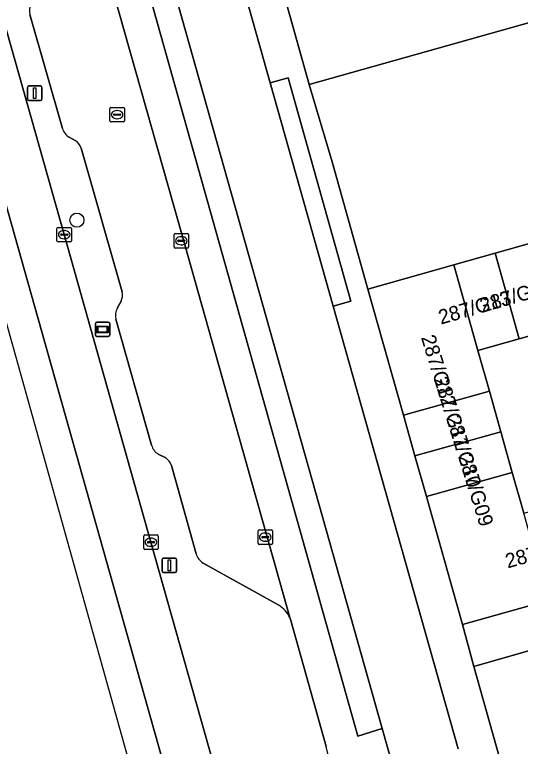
# Model space of a CAD drawing. Extents: x 159680 to 160786, y 387323 to 388340.
# Drawn here: x 159736.2 to 159770.9, y 387944.8 to 387995.1 of the extents above; entities that cross this region are included whole.
import ezdxf

# ---------------------------------------------------------------- set-up
doc = ezdxf.new("R2010")
doc.units = 0
for name, color, linetype in [('IMGEO_Berm_groen', 7, 'Continuous'), ('IMGEO_Boom', 7, 'Continuous'), ('IMGEO_Erf', 7, 'Continuous'), ('IMGEO_Kolk', 7, 'Continuous'), ('IMGEO_Lichtmast', 7, 'Continuous'), ('IMGEO_OVBaan_gesloten', 7, 'Continuous'), ('IMGEO_Pand', 7, 'Continuous'), ('IMGEO_Pand_nummerreeks', 7, 'Continuous'), ('IMGEO_Parkeervlak_open', 7, 'Continuous'), ('IMGEO_Rijbaan_lokaal_gesloten', 7, 'Continuous'), ('IMGEO_Rijbaan_lokaal_open', 7, 'Continuous'), ('IMGEO_Rijbaan_regionaal_gesloten', 7, 'Continuous'), ('IMGEO_Rioolput', 7, 'Continuous'), ('IMGEO_Voetpad_open', 7, 'Continuous'), ('IMGEO_Wegwijzer', 7, 'Continuous')]:
    doc.layers.add(name, color=color, linetype=linetype)

msp = doc.modelspace()

# ---------------------------------------------------------------- linework, layer by layer
at = {"layer": 'IMGEO_Berm_groen'}
for points in [[(159715.024, 388067.618), (159715.751, 388064.431), (159715.988, 388063.449), (159716.233, 388062.473), (159717.284, 388058.854), (159722.145, 388041.542), (159727.852, 388021.312), (159733.85, 388000.16), (159739.567, 387979.98), (159745.531, 387958.814), (159750.399, 387941.515), (159752.767, 387933.007), (159752.834, 387932.851)], [(159739.441, 387987.286), (159737.2, 387995.117)], [(159740.315, 387986.458), (159739.908, 387986.68)], [(159743.542, 387976.042), (159740.723, 387985.94)], [(159743.218, 387974.92), (159743.482, 387975.405)], [(159745.578, 387965.499), (159743.123, 387974.154)], [(159746.565, 387964.628), (159746.032, 387964.879)], [(159748.638, 387958.018), (159746.942, 387964.105)], [(159754.336, 387954.481), (159749.116, 387957.374)], [(159757.589, 387944.769), (159755.159, 387953.438), (159755.075, 387953.635)]]:
    msp.add_lwpolyline(points, dxfattribs=at)
for centre, radius, start, end in [((159738.236, 387995.366), 1.065, 151.5729, 193.506), ((159740.55, 387987.658), 1.17, 198.5337, 236.7039), ((159739.864, 387985.683), 0.897, 16.6604, 59.7907), ((159742.594, 387975.81), 0.976, 335.4919, 13.7463), ((159744.175, 387974.412), 1.083, 152.0546, 193.8058), ((159746.583, 387965.758), 1.038, 194.4791, 237.9484), ((159745.504, 387963.466), 1.573, 23.9627, 47.6085), ((159749.768, 387958.358), 1.18, 196.7211, 236.4471), ((159753.179, 387952.725), 2.103, 25.6488, 56.627), ((159746.164, 387941.8), 11.804, 335.9534, 14.5668)]:
    msp.add_arc(centre, radius, start, end, dxfattribs=at)
at = {"layer": 'IMGEO_Boom'}
msp.add_circle((159740.436, 387980.974), 0.489, dxfattribs=at)
at = {"layer": 'IMGEO_Erf'}
msp.add_lwpolyline([(159760.456, 387976.237), (159766.359, 387977.9), (159769.209, 387978.703), (159772.059, 387979.506), (159774.909, 387980.309), (159777.759, 387981.111), (159780.609, 387981.914), (159783.459, 387982.717), (159786.309, 387983.52), (159789.159, 387984.323), (159792.009, 387985.126), (159794.859, 387985.929), (159797.709, 387986.732), (159800.559, 387987.534), (159803.409, 387988.337), (159806.259, 387989.14), (159811.529, 387990.625), (159810.425, 387994.602), (159808.927, 388000), (159807.434, 388004.707), (159790.741, 388000), (159756.404, 387990.318), (159757.994, 387984.988), (159759.125, 387980.967)], close=True, dxfattribs=at)
msp.add_lwpolyline([(159779.046, 387953.498), (159767.731, 387950.268), (159771.07, 387938.458), (159771.513, 387937.282), (159767.279, 387929.559), (159770.394, 387918.296), (159773.512, 387907.023), (159776.309, 387897.203), (159779.471, 387885.959), (159782.637, 387874.792), (159785.606, 387864.46), (159788.041, 387856.178), (159790.71, 387847.415)], dxfattribs=at)
at = {"layer": 'IMGEO_Kolk'}
for p, q in [((159739.066, 387979.554), (159739.066, 387980.406)), ((159739.141, 387980.48), (159739.993, 387980.48)), ((159739.554, 387980.26), (159739.579, 387980.26)), ((159740.067, 387980.406), (159740.067, 387979.554)), ((159739.325, 387979.974), (159739.325, 387979.986)), ((159739.763, 387979.937), (159739.365, 387979.937)), ((159739.368, 387980.023), (159739.766, 387980.023)), ((159739.577, 387979.7), (159739.552, 387979.7)), ((159739.809, 387979.986), (159739.809, 387979.974)), ((159747.119, 387979.133), (159747.119, 387979.985)), ((159747.194, 387980.059), (159748.046, 387980.059)), ((159747.607, 387979.839), (159747.632, 387979.839)), ((159748.12, 387979.985), (159748.12, 387979.133)), ((159739.993, 387979.48), (159739.141, 387979.48)), ((159747.378, 387979.553), (159747.378, 387979.565)), ((159747.816, 387979.516), (159747.418, 387979.516)), ((159747.421, 387979.602), (159747.819, 387979.602)), ((159747.63, 387979.279), (159747.605, 387979.279)), ((159747.862, 387979.565), (159747.862, 387979.553)), ((159748.046, 387979.059), (159747.194, 387979.059)), ((159752.894, 387958.738), (159752.894, 387959.59)), ((159752.969, 387959.664), (159753.821, 387959.664)), ((159753.895, 387959.59), (159753.895, 387958.738)), ((159745.03, 387958.388), (159745.03, 387959.24)), ((159745.105, 387959.314), (159745.957, 387959.314)), ((159745.518, 387959.094), (159745.543, 387959.094)), ((159746.031, 387959.24), (159746.031, 387958.388)), ((159753.153, 387959.158), (159753.153, 387959.17)), ((159753.591, 387959.121), (159753.193, 387959.121)), ((159753.196, 387959.207), (159753.594, 387959.207)), ((159753.382, 387959.444), (159753.407, 387959.444)), ((159753.637, 387959.17), (159753.637, 387959.158)), ((159745.289, 387958.808), (159745.289, 387958.82)), ((159745.727, 387958.771), (159745.329, 387958.771)), ((159745.332, 387958.857), (159745.73, 387958.857)), ((159745.541, 387958.534), (159745.516, 387958.534)), ((159745.773, 387958.82), (159745.773, 387958.808)), ((159753.821, 387958.664), (159752.969, 387958.664)), ((159753.405, 387958.884), (159753.38, 387958.884)), ((159745.957, 387958.314), (159745.105, 387958.314))]:
    msp.add_line(p, q, dxfattribs=at)
for points in [[(159739.066, 387979.554), (159739.066, 387980.406)], [(159739.141, 387980.48), (159739.993, 387980.48)], [(159740.067, 387980.406), (159740.067, 387979.554)], [(159747.119, 387979.133), (159747.119, 387979.985)], [(159747.194, 387980.059), (159748.046, 387980.059)], [(159748.12, 387979.985), (159748.12, 387979.133)], [(159739.993, 387979.48), (159739.141, 387979.48)], [(159748.046, 387979.059), (159747.194, 387979.059)], [(159752.894, 387958.738), (159752.894, 387959.59)], [(159752.969, 387959.664), (159753.821, 387959.664)], [(159753.895, 387959.59), (159753.895, 387958.738)], [(159745.03, 387958.388), (159745.03, 387959.24)], [(159745.105, 387959.314), (159745.957, 387959.314)], [(159746.031, 387959.24), (159746.031, 387958.388)], [(159753.821, 387958.664), (159752.969, 387958.664)], [(159745.957, 387958.314), (159745.105, 387958.314)]]:
    msp.add_lwpolyline(points, dxfattribs=at)
for centre, radius, start, end in [((159739.143, 387980.404), 0.0765, 91.552, 178.448), ((159739.143, 387980.404), 0.0765, 91.552, 178.448), ((159739.991, 387980.404), 0.0765, 1.552, 88.448), ((159739.991, 387980.404), 0.0765, 1.552, 88.448), ((159739.365, 387979.983), 0.0403, 85.8775, 175.7526), ((159739.362, 387979.973), 0.0366, 178.938, 274.7102), ((159739.766, 387979.98), 0.043, 264.8664, 352.4533), ((159739.77, 387979.985), 0.0386, 1.7309, 96.639), ((159747.196, 387979.983), 0.0765, 91.552, 178.448), ((159747.196, 387979.983), 0.0765, 91.552, 178.448), ((159748.044, 387979.983), 0.0765, 1.552, 88.448), ((159748.044, 387979.983), 0.0765, 1.552, 88.448), ((159739.143, 387979.556), 0.0765, 181.552, 268.448), ((159739.143, 387979.556), 0.0765, 181.552, 268.448), ((159739.991, 387979.556), 0.0765, 271.552, 358.448), ((159739.991, 387979.556), 0.0765, 271.552, 358.448), ((159747.418, 387979.562), 0.0403, 85.8775, 175.7526), ((159747.415, 387979.552), 0.0366, 178.938, 274.7102), ((159747.819, 387979.559), 0.043, 264.8664, 352.4533), ((159747.823, 387979.564), 0.0386, 1.7309, 96.639), ((159747.196, 387979.135), 0.0765, 181.552, 268.448), ((159747.196, 387979.135), 0.0765, 181.552, 268.448), ((159748.044, 387979.135), 0.0765, 271.552, 358.448), ((159748.044, 387979.135), 0.0765, 271.552, 358.448), ((159752.971, 387959.588), 0.0765, 91.552, 178.448), ((159752.971, 387959.588), 0.0765, 91.552, 178.448), ((159753.819, 387959.588), 0.0765, 1.552, 88.448), ((159753.819, 387959.588), 0.0765, 1.552, 88.448), ((159745.107, 387959.238), 0.0765, 91.552, 178.448), ((159745.107, 387959.238), 0.0765, 91.552, 178.448), ((159745.955, 387959.238), 0.0765, 1.552, 88.448), ((159745.955, 387959.238), 0.0765, 1.552, 88.448), ((159753.193, 387959.167), 0.0403, 85.8775, 175.7526), ((159753.19, 387959.157), 0.0366, 178.938, 274.7102), ((159753.594, 387959.164), 0.043, 264.8664, 352.4533), ((159753.598, 387959.169), 0.0386, 1.7309, 96.639), ((159745.329, 387958.817), 0.0403, 85.8775, 175.7526), ((159745.326, 387958.807), 0.0366, 178.938, 274.7102), ((159745.73, 387958.814), 0.043, 264.8664, 352.4533), ((159745.734, 387958.819), 0.0386, 1.7309, 96.639), ((159752.971, 387958.74), 0.0765, 181.552, 268.448), ((159752.971, 387958.74), 0.0765, 181.552, 268.448), ((159753.819, 387958.74), 0.0765, 271.552, 358.448), ((159753.819, 387958.74), 0.0765, 271.552, 358.448), ((159745.107, 387958.39), 0.0765, 181.552, 268.448), ((159745.107, 387958.39), 0.0765, 181.552, 268.448), ((159745.955, 387958.39), 0.0765, 271.552, 358.448), ((159745.955, 387958.39), 0.0765, 271.552, 358.448)]:
    msp.add_arc(centre, radius, start, end, dxfattribs=at)
for centre, major_axis, ratio, start_param, end_param in [((159739.553, 387979.98), (-0.387, 0.002), 0.722429, 4.712389, 7.853982), ((159739.578, 387979.98), (-0.39, 0.002), 0.717154, 1.570796, 4.712389), ((159747.606, 387979.559), (-0.387, 0.002), 0.722429, 4.712389, 7.853982), ((159747.631, 387979.559), (-0.39, 0.002), 0.717154, 1.570796, 4.712389), ((159745.517, 387958.814), (-0.387, 0.002), 0.722429, 4.712389, 7.853982), ((159745.542, 387958.814), (-0.39, 0.002), 0.717154, 1.570796, 4.712389), ((159753.381, 387959.164), (-0.387, 0.002), 0.722429, 4.712389, 7.853982), ((159753.406, 387959.164), (-0.39, 0.002), 0.717154, 1.570796, 4.712389)]:
    msp.add_ellipse(centre, major_axis=major_axis, ratio=ratio, start_param=start_param, end_param=end_param, dxfattribs=at)
at = {"layer": 'IMGEO_Lichtmast'}
for p, q in [((159737.039, 387989.311), (159737.039, 387990.111)), ((159737.039, 387990.111), (159737.039, 387989.311)), ((159737.139, 387990.211), (159737.929, 387990.211)), ((159737.929, 387990.211), (159737.139, 387990.211)), ((159738.029, 387990.111), (159738.029, 387989.311)), ((159738.029, 387989.311), (159738.029, 387990.111)), ((159737.929, 387989.211), (159737.139, 387989.211)), ((159737.139, 387989.211), (159737.929, 387989.211)), ((159746.305, 387956.829), (159746.305, 387957.629)), ((159746.305, 387957.629), (159746.305, 387956.829)), ((159746.405, 387957.729), (159747.195, 387957.729)), ((159747.195, 387957.729), (159746.405, 387957.729)), ((159747.295, 387957.629), (159747.295, 387956.829)), ((159747.295, 387956.829), (159747.295, 387957.629)), ((159747.195, 387956.729), (159746.405, 387956.729)), ((159746.405, 387956.729), (159747.195, 387956.729))]:
    msp.add_line(p, q, dxfattribs=at)
for points in [[(159737.459, 387990.086), (159737.609, 387990.086), (159737.609, 387989.336), (159737.459, 387989.336), (159737.459, 387990.086)], [(159746.725, 387957.604), (159746.875, 387957.604), (159746.875, 387956.854), (159746.725, 387956.854), (159746.725, 387957.604)]]:
    msp.add_lwpolyline(points, dxfattribs=at)
for centre, start, end in [((159737.139, 387990.111), 90, 180), ((159737.139, 387990.111), 90, 180), ((159737.929, 387990.111), 0, 90), ((159737.929, 387990.111), 360, 90), ((159737.139, 387989.311), 180, 270), ((159737.139, 387989.311), 180, 270), ((159737.929, 387989.311), 270, 0), ((159737.929, 387989.311), 270, 0), ((159746.405, 387957.629), 90, 180), ((159746.405, 387957.629), 90, 180), ((159747.195, 387957.629), 0, 90), ((159747.195, 387957.629), 360, 90), ((159746.405, 387956.829), 180, 270), ((159746.405, 387956.829), 180, 270), ((159747.195, 387956.829), 270, 0), ((159747.195, 387956.829), 270, 0)]:
    msp.add_arc(centre, 0.1, start, end, dxfattribs=at)
at = {"layer": 'IMGEO_OVBaan_gesloten'}
for points in [[(159702.382, 388092.39), (159734.05, 387979.268), (159743.358, 387946.02), (159763.999, 387872.286), (159769.025, 387858.073)], [(159767.423, 387866.904), (159767.598, 387866.954), (159765.544, 387875.18), (159761.072, 387891.211), (159751.402, 387925.737), (159750.981, 387927.311), (159738.22, 387972.552), (159720.318, 388036.089), (159710.692, 388070.166), (159709.458, 388074.221)]]:
    msp.add_lwpolyline(points, dxfattribs=at)
at = {"layer": 'IMGEO_Pand'}
for points in [[(159802.49, 388022.293), (159801.523, 388025.732), (159795.233, 388048.104), (159794.855, 388047.996), (159776.16, 388042.673), (159744.329, 388033.5), (159753.697, 388000), (159756.404, 387990.318), (159790.741, 388000), (159807.434, 388004.707)], [(159773.717, 387973.619), (159772.059, 387979.506), (159769.209, 387978.703), (159770.867, 387972.816)], [(159770.867, 387972.816), (159769.209, 387978.703), (159766.359, 387977.9), (159768.017, 387972.013)], [(159762.903, 387967.55), (159768.806, 387969.213), (159768.017, 387972.013), (159766.359, 387977.9), (159760.456, 387976.237)], [(159762.903, 387967.55), (159763.692, 387964.751), (159769.594, 387966.414), (159768.806, 387969.213)], [(159764.48, 387961.951), (159770.383, 387963.614), (159769.594, 387966.414), (159763.692, 387964.751)], [(159764.48, 387961.951), (159766.959, 387953.152), (159772.862, 387954.815), (159771.172, 387960.814), (159770.383, 387963.614)]]:
    msp.add_lwpolyline(points, close=True, dxfattribs=at)
at = {"layer": 'IMGEO_Parkeervlak_open'}
for points in [[(159725.402, 388073.744), (159725.596, 388072.962), (159730.011, 388057.458), (159734.238, 388042.443), (159743.795, 388008.597), (159761.428, 387945.993), (159764.329, 387935.795)], [(159755.075, 387953.635), (159747.858, 387979.284), (159736.534, 388019.31), (159725.379, 388059.003)], [(159766.666, 387944.588), (159758.06, 387975.063), (159753.727, 387990.417), (159748.666, 388008.437), (159739.318, 388041.629)], [(159737.2, 387995.117), (159739.441, 387987.286)], [(159739.908, 387986.68), (159740.315, 387986.458)], [(159740.723, 387985.94), (159743.542, 387976.042)], [(159743.482, 387975.405), (159743.218, 387974.92)], [(159743.123, 387974.154), (159745.578, 387965.499)], [(159746.032, 387964.879), (159746.565, 387964.628)], [(159746.942, 387964.105), (159748.638, 387958.018)], [(159749.116, 387957.374), (159754.336, 387954.481)]]:
    msp.add_lwpolyline(points, dxfattribs=at)
for centre, radius, start, end in [((159738.236, 387995.366), 1.065, 151.5729, 193.506), ((159740.55, 387987.658), 1.17, 198.5337, 236.7039), ((159739.864, 387985.683), 0.897, 16.6604, 59.7907), ((159742.594, 387975.81), 0.976, 335.4919, 13.7463), ((159744.175, 387974.412), 1.083, 152.0546, 193.8058), ((159746.583, 387965.758), 1.038, 194.4791, 237.9484), ((159745.504, 387963.466), 1.573, 23.9627, 47.6085), ((159749.768, 387958.358), 1.18, 196.7211, 236.4471), ((159753.179, 387952.725), 2.103, 25.6488, 56.627)]:
    msp.add_arc(centre, radius, start, end, dxfattribs=at)
at = {"layer": 'IMGEO_Rijbaan_lokaal_gesloten'}
msp.add_lwpolyline([(159734.238, 388042.443), (159730.011, 388057.458), (159725.596, 388072.962), (159723.956, 388072.484), (159728.319, 388056.998), (159732.531, 388042.133), (159742.233, 388007.83), (159759.756, 387945.476), (159761.428, 387945.993), (159743.795, 388008.597)], close=True, dxfattribs=at)
for points in [[(159724.374, 388062.612), (159725.379, 388059.003), (159736.534, 388019.31), (159747.858, 387979.284), (159755.075, 387953.635), (159755.159, 387953.438), (159757.589, 387944.769)], [(159764.329, 387935.795), (159761.428, 387945.993), (159759.756, 387945.476), (159742.233, 388007.83)]]:
    msp.add_lwpolyline(points, dxfattribs=at)
msp.add_arc((159746.164, 387941.8), 11.804, 335.9534, 14.5668, dxfattribs=at)
at = {"layer": 'IMGEO_Rijbaan_lokaal_open'}
msp.add_lwpolyline([(159793.667, 387979.239), (159790.817, 387978.436), (159787.967, 387977.633), (159785.117, 387976.83), (159782.267, 387976.027), (159779.417, 387975.224), (159776.567, 387974.422), (159773.717, 387973.619), (159770.867, 387972.816), (159768.017, 387972.013), (159768.806, 387969.213), (159769.594, 387966.414), (159770.383, 387963.614), (159771.172, 387960.814), (159774.022, 387961.617), (159776.872, 387962.42), (159779.722, 387963.223), (159782.572, 387964.026), (159785.422, 387964.829), (159788.272, 387965.632), (159791.122, 387966.434)], dxfattribs=at)
at = {"layer": 'IMGEO_Rijbaan_regionaal_gesloten'}
for points in [[(159761.123, 387913.424), (159760.298, 387915.464), (159759.456, 387917.543), (159752.834, 387932.851), (159752.767, 387933.007), (159750.399, 387941.515), (159745.531, 387958.814), (159739.567, 387979.98), (159733.85, 388000.16), (159727.852, 388021.312), (159722.145, 388041.542), (159717.284, 388058.854), (159716.233, 388062.473), (159715.988, 388063.449), (159715.751, 388064.431), (159715.024, 388067.618), (159715.019, 388067.661), (159714.041, 388082.364), (159713.601, 388085.431)], [(159709.458, 388074.221), (159710.692, 388070.166), (159720.318, 388036.089), (159738.22, 387972.552), (159750.981, 387927.311), (159751.402, 387925.737), (159761.072, 387891.211), (159765.544, 387875.18)]]:
    msp.add_lwpolyline(points, dxfattribs=at)
at = {"layer": 'IMGEO_Rioolput'}
for p, q in [((159742.704, 387987.809), (159742.704, 387988.661)), ((159742.779, 387988.735), (159743.631, 387988.735)), ((159742.963, 387988.229), (159742.963, 387988.241)), ((159743.006, 387988.278), (159743.404, 387988.278)), ((159743.192, 387988.515), (159743.217, 387988.515)), ((159743.447, 387988.241), (159743.447, 387988.229)), ((159743.705, 387988.661), (159743.705, 387987.809)), ((159743.631, 387987.735), (159742.779, 387987.735)), ((159743.401, 387988.192), (159743.003, 387988.192)), ((159743.215, 387987.955), (159743.19, 387987.955))]:
    msp.add_line(p, q, dxfattribs=at)
for points in [[(159742.704, 387987.809), (159742.704, 387988.661)], [(159742.779, 387988.735), (159743.631, 387988.735)], [(159743.705, 387988.661), (159743.705, 387987.809)], [(159743.631, 387987.735), (159742.779, 387987.735)]]:
    msp.add_lwpolyline(points, dxfattribs=at)
for centre, radius, start, end in [((159742.781, 387988.659), 0.0765, 91.552, 178.448), ((159742.781, 387988.659), 0.0765, 91.552, 178.448), ((159743.003, 387988.238), 0.0403, 85.8775, 175.7526), ((159743.408, 387988.24), 0.0386, 1.7309, 96.639), ((159743.629, 387988.659), 0.0765, 1.552, 88.448), ((159743.629, 387988.659), 0.0765, 1.552, 88.448), ((159742.781, 387987.811), 0.0765, 181.552, 268.448), ((159742.781, 387987.811), 0.0765, 181.552, 268.448), ((159743, 387988.228), 0.0366, 178.938, 274.7102), ((159743.404, 387988.235), 0.043, 264.8664, 352.4533), ((159743.629, 387987.811), 0.0765, 271.552, 358.448), ((159743.629, 387987.811), 0.0765, 271.552, 358.448)]:
    msp.add_arc(centre, radius, start, end, dxfattribs=at)
for centre, major_axis, ratio, start_param, end_param in [((159743.191, 387988.235), (-0.387, 0.002), 0.722429, 4.712389, 7.853982), ((159743.216, 387988.235), (-0.39, 0.002), 0.717154, 1.570796, 4.712389)]:
    msp.add_ellipse(centre, major_axis=major_axis, ratio=ratio, start_param=start_param, end_param=end_param, dxfattribs=at)
at = {"layer": 'IMGEO_Voetpad_open'}
for points in [[(159726.812, 388085.698), (159730.577, 388072.488), (159731.786, 388072.824), (159733.725, 388066.059), (159732.509, 388065.712), (159737.631, 388047.595), (159738.793, 388047.914), (159740.51, 388041.947), (159739.318, 388041.629), (159748.666, 388008.437), (159753.727, 387990.417), (159754.963, 387990.761), (159759.29, 387975.401), (159758.06, 387975.063), (159766.666, 387944.588)], [(159782.637, 387874.792), (159779.471, 387885.959), (159776.309, 387897.203), (159773.512, 387907.023), (159770.394, 387918.296), (159767.279, 387929.559), (159765.672, 387935.371), (159769.038, 387936.324), (159768.65, 387937.819), (159771.07, 387938.458), (159767.731, 387950.268), (159766.959, 387953.152), (159764.48, 387961.951), (159763.692, 387964.751), (159762.903, 387967.55), (159760.456, 387976.237), (159759.125, 387980.967), (159757.994, 387984.988), (159756.404, 387990.318), (159753.697, 388000)], [(159792.812, 387960.435), (159789.962, 387959.632), (159787.112, 387958.829), (159784.262, 387958.027), (159781.412, 387957.224), (159778.562, 387956.421), (159775.712, 387955.618), (159772.862, 387954.815), (159766.959, 387953.152), (159767.731, 387950.268), (159779.046, 387953.498), (159790.044, 387956.547), (159795.499, 387958.055)]]:
    msp.add_lwpolyline(points, dxfattribs=at)
msp.add_lwpolyline([(159753.727, 387990.417), (159758.06, 387975.063), (159759.29, 387975.401), (159754.963, 387990.761)], close=True, dxfattribs=at)
at = {"layer": 'IMGEO_Wegwijzer'}
for p, q in [((159741.705, 387973.06), (159741.705, 387973.86)), ((159741.705, 387973.86), (159741.705, 387973.06)), ((159741.805, 387973.96), (159742.595, 387973.96)), ((159742.595, 387973.96), (159741.805, 387973.96)), ((159742.695, 387973.86), (159742.695, 387973.06)), ((159742.695, 387973.06), (159742.695, 387973.86)), ((159742.595, 387972.96), (159741.805, 387972.96)), ((159741.805, 387972.96), (159742.595, 387972.96))]:
    msp.add_line(p, q, dxfattribs=at)
for points in [[(159741.806, 387973.692), (159742.594, 387973.692), (159742.594, 387973.228), (159741.806, 387973.228), (159741.806, 387973.692)], [(159741.871, 387973.627), (159741.871, 387973.293), (159742.529, 387973.293), (159742.529, 387973.627), (159741.871, 387973.627)]]:
    msp.add_lwpolyline(points, dxfattribs=at)
for centre, start, end in [((159741.805, 387973.86), 90, 180), ((159741.805, 387973.86), 90, 180), ((159742.595, 387973.86), 0, 90), ((159742.595, 387973.86), 360, 90), ((159741.805, 387973.06), 180, 270), ((159741.805, 387973.06), 180, 270), ((159742.595, 387973.06), 270, 0), ((159742.595, 387973.06), 270, 0)]:
    msp.add_arc(centre, 0.1, start, end, dxfattribs=at)

# ---------------------------------------------------------------- texts
at = {"layer": 'IMGEO_Pand_nummerreeks'}
for s, rotation, p in [('287/G14', 16.0244, (159768.321, 387974.604)), ('287/G13', 16.0244, (159765.472, 387973.786)), ('287/G12', 287.2924, (159764.095, 387972.908)), ('287/G11', 287.2924, (159764.989, 387970.036)), ('287/G10', 287.2924, (159765.816, 387967.378)), ('287/G09', 287.2924, (159766.647, 387964.71)), ('287/G08', 15.6728, (159770.069, 387957.011))]:
    msp.add_text(s, height=1, rotation=rotation, dxfattribs=at).set_placement(p)

doc.saveas('drawing.dxf')
